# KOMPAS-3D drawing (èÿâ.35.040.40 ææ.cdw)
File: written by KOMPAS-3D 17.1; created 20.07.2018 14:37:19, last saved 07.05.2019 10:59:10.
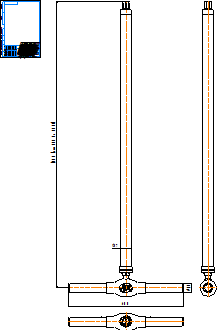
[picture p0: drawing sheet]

Sheet 1: A4, portrait

Title block, sheet 1: name: КШГ.35.040.40 СС; material: Внимание! Данный продукт является объектом авторского права ООО «Торговый Дом АДЛ». / Запрещается изменение, копирование, распространение / (в том числе путем копирования на другие сайты и ресурсы в Интернете) / или любое иное использование информации и объектов без предварительного / согласия правообладателя (ООО «Торговый Дом АДЛ»).; sheets: 1; organisation: ООО "Торговый дом АДЛ"; sheet format: A4; stored path: C:\Users\tra\Desktop\2д чертежи\Шаровые краны БИВАЛ\КШ_Бивал_серия_34_35\KOMPAS 2D\КШГ.35.040.40 СС.cdw

Views: Вид 1, Проекционный вид 2, Проекционный вид 3
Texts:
  kka
  adl
  (от 250 до 5000)
Dimensions and other numbers on the sheet: 600; 48; 1500; 57; 1:1; 1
